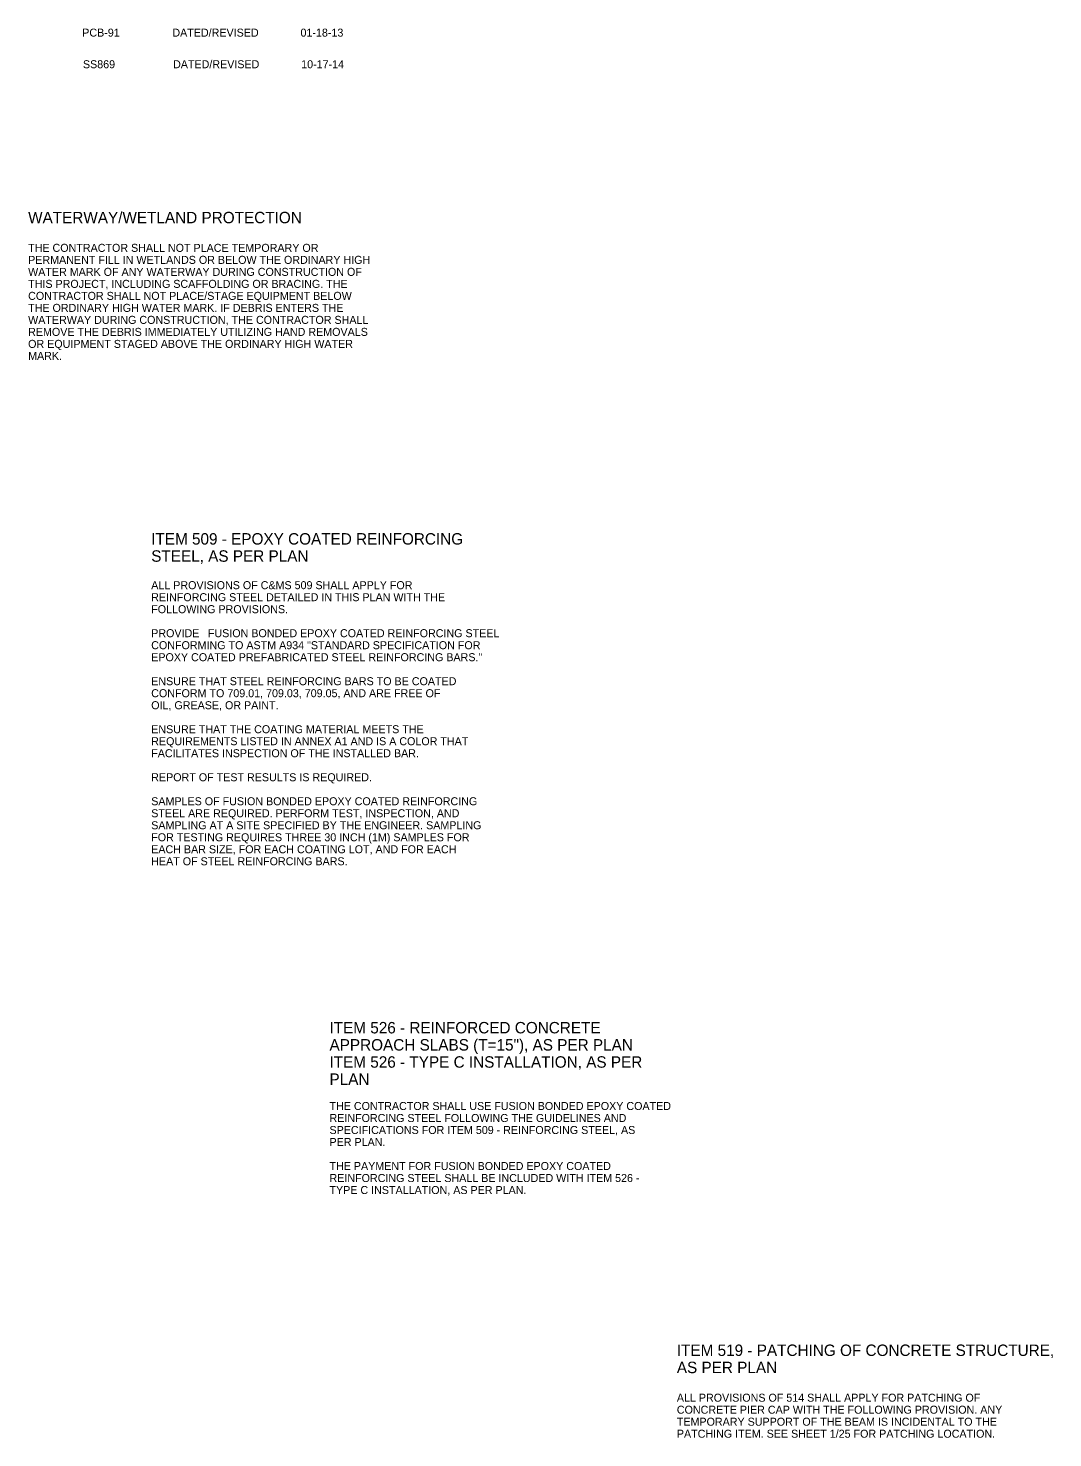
# Model space of a CAD drawing. Extents: x -51.6 to 45.5, y -38.3 to 35.3.
# Drawn here: x -46.74 to -28.82, y -38.26 to -13.6 of the extents above; entities that cross this region are included whole.
import ezdxf

# ---------------------------------------------------------------- set-up
doc = ezdxf.new("R2010")
doc.units = 0
doc.layers.add('SH_Text', color=7, linetype='Continuous')

msp = doc.modelspace()

# ---------------------------------------------------------------- texts
at = {"layer": 'SH_Text'}
for s, height, p in [('  PCB-91', 0.14, (-45.896, -13.746)), ('DATED/REVISED', 0.14, (-44.216, -13.746)), ('01-18-13', 0.14, (-41.976, -13.746)), ('  SS869', 0.14, (-45.884, -14.299)), ('DATED/REVISED', 0.14, (-44.204, -14.299)), ('10-17-14', 0.14, (-41.964, -14.299)), ('WATERWAY/WETLAND PROTECTION', 0.2, (-46.738, -17.011)), ('THE CONTRACTOR SHALL NOT PLACE TEMPORARY OR ', 0.14, (-46.738, -17.511)), ('PERMANENT FILL IN WETLANDS OR BELOW THE ORDINARY HIGH ', 0.14, (-46.738, -17.721)), ('WATER MARK OF ANY WATERWAY DURING CONSTRUCTION OF ', 0.14, (-46.738, -17.931)), ('THIS PROJECT, INCLUDING SCAFFOLDING OR BRACING. THE ', 0.14, (-46.738, -18.141)), ('CONTRACTOR SHALL NOT PLACE/STAGE EQUIPMENT BELOW ', 0.14, (-46.738, -18.351)), ('THE ORDINARY HIGH WATER MARK. IF DEBRIS ENTERS THE ', 0.14, (-46.738, -18.561)), ('WATERWAY DURING CONSTRUCTION, THE CONTRACTOR SHALL ', 0.14, (-46.738, -18.771)), ('REMOVE THE DEBRIS IMMEDIATELY UTILIZING HAND REMOVALS ', 0.14, (-46.738, -18.981)), ('OR EQUIPMENT STAGED ABOVE THE ORDINARY HIGH WATER ', 0.14, (-46.738, -19.191)), ('MARK.', 0.14, (-46.738, -19.401)), ('ITEM 509 - EPOXY COATED REINFORCING ', 0.2, (-44.586, -22.632)), ('STEEL, AS PER PLAN', 0.2, (-44.586, -22.932)), ('ALL PROVISIONS OF C&MS 509 SHALL APPLY FOR ', 0.14, (-44.586, -23.412)), ('REINFORCING STEEL DETAILED IN THIS PLAN WITH THE ', 0.14, (-44.586, -23.622)), ('FOLLOWING PROVISIONS.', 0.14, (-44.586, -23.832)), ('PROVIDE ', 0.14, (-44.586, -24.252)), ('FUSION BONDED EPOXY COATED REINFORCING STEEL', 0.14, (-43.595, -24.252)), ('CONFORMING TO ASTM A934 "STANDARD SPECIFICATION FOR ', 0.14, (-44.586, -24.462)), ('EPOXY COATED PREFABRICATED STEEL REINFORCING BARS."', 0.14, (-44.586, -24.672)), ('ENSURE THAT STEEL REINFORCING BARS TO BE COATED ', 0.14, (-44.586, -25.092)), ('CONFORM TO 709.01, 709.03, 709.05, AND ARE FREE OF ', 0.14, (-44.586, -25.302)), ('OIL, GREASE, OR PAINT.', 0.14, (-44.586, -25.512)), ('ENSURE THAT THE COATING MATERIAL MEETS THE ', 0.14, (-44.586, -25.932)), ('REQUIREMENTS LISTED IN ANNEX A1 AND IS A COLOR THAT ', 0.14, (-44.586, -26.142)), ('FACILITATES INSPECTION OF THE INSTALLED BAR.', 0.14, (-44.586, -26.352)), ('REPORT OF TEST RESULTS IS REQUIRED.', 0.14, (-44.586, -26.772)), ('SAMPLES OF FUSION BONDED EPOXY COATED REINFORCING ', 0.14, (-44.586, -27.192)), ('STEEL ARE REQUIRED. PERFORM TEST, INSPECTION, AND ', 0.14, (-44.586, -27.402)), ('SAMPLING AT A SITE SPECIFIED BY THE ENGINEER. SAMPLING ', 0.14, (-44.586, -27.612)), ('FOR TESTING REQUIRES THREE 30 INCH (1M) SAMPLES FOR ', 0.14, (-44.586, -27.822)), ('EACH BAR SIZE, FOR EACH COATING LOT, AND FOR EACH ', 0.14, (-44.586, -28.032)), ('HEAT OF STEEL REINFORCING BARS.', 0.14, (-44.586, -28.242)), ('ITEM 526 - REINFORCED CONCRETE ', 0.2, (-41.469, -31.183)), ('APPROACH SLABS (T=15"), AS PER PLAN', 0.2, (-41.469, -31.483)), ('ITEM 526 - TYPE C INSTALLATION, AS PER ', 0.2, (-41.469, -31.783)), ('PLAN', 0.2, (-41.469, -32.083)), ('THE CONTRACTOR SHALL USE FUSION BONDED EPOXY COATED ', 0.14, (-41.469, -32.523)), ('REINFORCING STEEL FOLLOWING THE GUIDELINES AND ', 0.14, (-41.469, -32.733)), ('SPECIFICATIONS FOR ITEM 509 - REINFORCING STEEL, AS ', 0.14, (-41.469, -32.943)), ('PER PLAN.', 0.14, (-41.469, -33.153)), ('THE PAYMENT FOR FUSION BONDED EPOXY COATED ', 0.14, (-41.469, -33.573)), ('REINFORCING STEEL SHALL BE INCLUDED WITH ITEM 526 - ', 0.14, (-41.469, -33.783)), ('TYPE C INSTALLATION, AS PER PLAN.', 0.14, (-41.469, -33.993)), ('ITEM 519 - PATCHING OF CONCRETE STRUCTURE, ', 0.2, (-35.396, -36.826)), ('AS PER PLAN', 0.2, (-35.396, -37.126)), ('ALL PROVISIONS OF 514 SHALL APPLY FOR PATCHING OF ', 0.14, (-35.396, -37.626)), ('CONCRETE PIER CAP WITH THE FOLLOWING PROVISION. ANY ', 0.14, (-35.396, -37.836)), ('TEMPORARY SUPPORT OF THE BEAM IS INCIDENTAL TO THE ', 0.14, (-35.396, -38.046)), ('PATCHING ITEM. SEE SHEET 1/25 FOR PATCHING LOCATION.', 0.14, (-35.396, -38.256))]:
    msp.add_text(s, height=height, dxfattribs=at).set_placement(p)

doc.saveas('drawing.dxf')
